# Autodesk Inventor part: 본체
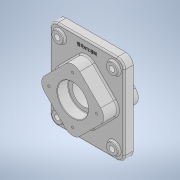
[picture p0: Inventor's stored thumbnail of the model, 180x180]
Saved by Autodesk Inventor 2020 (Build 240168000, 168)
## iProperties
Created: 2021-07
Part Number: 본체
Material: 일반
Document SubType Name: Modeling
Designer: Owner
Density: 1 g/cm^3
Appearance: 기본값
Mass: 807.982 g
Surface Area: 961.752 cm^2
Volume: 807.982 cm^3
Author: Owner
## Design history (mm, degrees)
sketch "스케치1"
  geometry: L1 (-75, 90)-(75, 90); L2 (75, 90)-(75, -90); L3 (75, -90)-(-75, -90); L4 (-75, -90)-(-75, 90); L5 (-75, 90)-(75, -90); L6 (75, 90)-(-75, -90); 1 further point
  constraints: 12 end point, 2 midpoint, 2 parallel, 1 horizontal, 1 perpendicular
  dimensions: "d0" = 150 distance of L2.end L3.end; "d1" = 180 distance of L1.end L2.end
extrude "돌출1" new body sketch "스케치1" distance "d2" = 18; taper "d3" = 0 deg
sketch "스케치2"
  geometry: L1 (-70.711, 0)-(0, 70.711); L2 (0, 70.711)-(70.711, 0); L3 (70.711, 0)-(0, -70.711); L4 (0, -70.711)-(-70.711, 0); L5 (-70.711, 0)-(70.711, 0); L6 (0, 70.711)-(0, -70.711); 2 further points
  constraints: 12 end point, 3 midpoint, 2 parallel, 1 perpendicular, 1 vertical alignment
  dimensions: "d4" = 100 distance between parallel lines of L2 L4; "d5" = 100 distance between parallel lines of L3 L1
extrude "돌출2" join sketch "스케치2" distance "d6" = 29; taper "d7" = 0 deg
extrude "돌출3" join sketch "스케치2" distance "d8" = 41; taper "d9" = 0 deg
fillet "모깎기1" dims "d10" = 20
sketch "스케치3"
  geometry: C1 r 31 at (0, 0); 1 further point
  constraints: 1 centre point, 1 coincident
  dimensions: "d11" = 62 diameter of C1
extrude "돌출4" cut sketch "스케치3" distance "d12" = 22; taper "d13" = 0 deg
sketch "스케치4"
  geometry: C1 r 22.5 at (0, 0); 1 further point
  constraints: 1 centre point, 1 coincident
  dimensions: "d14" = 45 diameter of C1
extrude "돌출5" cut sketch "스케치4" distance "d15" = 23; taper "d16" = 0 deg
sketch "스케치5"
  geometry: C1 r 22.5 at (0, 0) reference; C2 r 31 at (0, 0); 1 further point
  constraints: 1 centre point, 1 coincident
  dimensions: "d17" = 62 diameter of C2
extrude "돌출6" cut sketch "스케치5" distance "d18" = 22; taper "d19" = 0 deg
fillet "모깎기2" dims "d20" = 15
sketch "스케치6"
  geometry: L1 (-55, 70)-(55, 70); C1 r 11 at (-55, 70); C2 r 11 at (55, 70); 2 further points
  constraints: 2 centre point, 2 end point, 1 horizontal, 1 midpoint, 1 vertical alignment
  dimensions: "d21" = 22 diameter of C1; "d22" = 22 diameter of C2; "d23" = 110 distance of L1.start L1.end; "d24" = 70 distance of point (0, 0) point (0, 70)
extrude "돌출7" join sketch "스케치6" distance "d25" = 5; taper "d26" = 0 deg
sketch "스케치7"
  geometry: C1 r 11 at (0, 0) reference; 2 further points
  constraints: 1 coincident
hole "구멍1" sketch "스케치7" at (0, 0) diameter "d27" = 11; stored, may be unused: countersink angle "d31" = 90 deg, drill point angle "d33" = 0 deg; dims "d28" = 6, "d29" = 4, "d30" = 2, "d32" = 10
sketch "스케치8"
  geometry: C1 r 11 at (0, 0) reference; 2 further points
  constraints: 1 coincident
hole "구멍2" sketch "스케치8" at (0, 0) diameter "d34" = 11; stored, may be unused: countersink angle "d38" = 90 deg, drill point angle "d40" = 0 deg; dims "d35" = 6, "d36" = 4, "d37" = 2, "d39" = 10
fillet "모깎기3" dims "d41" = 20
sketch "스케치9" dims "d42" = 96
  geometry: C1 r 3 at (0, 48); 2 further points
  constraints: 1 centre point, 1 coincident, 1 vertical alignment, 2 other
  dimensions: "d43" = 6 diameter of C1
hole "구멍3" sketch "스케치9" at (0, 48) diameter "d44" = 4.917; stored, may be unused: countersink angle "d48" = 90 deg, drill point angle "d50" = 118 deg; dims "d45" = 10, "d46" = 4, "d47" = 2, "d49" = 13
fillet "모깎기4" dims "d54" = 1
chamfer "모따기1" distance "d55" = 1; stored, may be unused: second distance "d56" = 2, angle "d57" = 45 deg
fillet "모깎기5" dims "d58" = 1
chamfer "모따기2" distance "d59" = 1; stored, may be unused: second distance "d60" = 2, angle "d61" = 45 deg
sketch "스케치10"
  geometry: C1 r 22.5 at (0, 0); 1 further point
  constraints: 1 centre point, 1 coincident
  dimensions: "d62" = 45 diameter of C1
extrude "돌출8" cut sketch "스케치10" distance "d63" = 29; taper "d64" = 0 deg
fillet "모깎기6" dims "d65" = 3
fillet "모깎기7" dims "d66" = 3
fillet "모깎기8" dims "d67" = 3
sketch "스케치11"
  geometry: L1 (60, 90)-(-60, 90) reference; 2 further points
  constraints: 1 vertical alignment, 1 other
  dimensions: "d68" = 15 distance from line of point (0, 75) L1
feature "엠보싱1" sketch "스케치11" dims "d0" = 150, "d1" = 180, "d69" = 0.5, "d70" = 0
sketch "스케치12"
  geometry: C1 r 48 at (0, 0); C2 r 2.458 at (0, 48) reference; C3 r 3 at (0, 48); 1 further point
  constraints: 2 centre point, 2 coincident
  dimensions: "d71" = 96 diameter of C1; "d72" = 6 diameter of C3
hole "구멍4" sketch "스케치12" at (0, 48) diameter "d73" = 4.917; stored, may be unused: countersink angle "d77" = 90 deg, drill point angle "d79" = 118 deg; dims "d74" = 10, "d75" = 4, "d76" = 2, "d78" = 13
fillet "모깎기9" dims "d83" = 3
node "솔리드1"
mirror "미러1"
pattern_circular "원형 패턴1" dims angle "d52" = 360 deg
pattern_circular "원형 패턴2" dims angle "d81" = 360 deg
feature "A9D066F2-1C7D-4E18-AEED-F7BC21143FA4" dims "d27" = 11, "d28" = 6, "d29" = 4, "d30" = 2, "d31" = 90 deg, "d32" = 10, "d33" = 0
